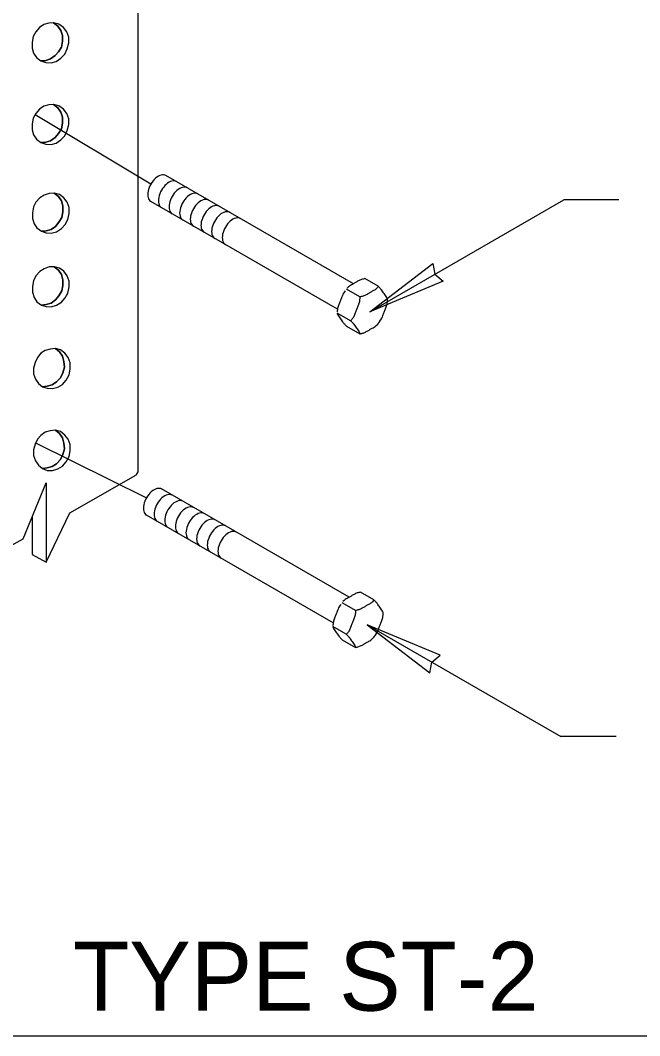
# Model space of a CAD drawing. Extents: x 99862 to 103680, y 99470 to 102076.
# Drawn here: x 100879.3 to 101059.2, y 99999.5 to 100294.4 of the extents above; entities that cross this region are included whole.
import ezdxf

# ---------------------------------------------------------------- set-up
doc = ezdxf.new("R2010")
doc.units = 0
for name, color, linetype in [('Level 1', 7, 'Continuous'), ('Level 13', 7, 'Continuous'), ('Level 15', 7, 'Continuous'), ('Level 2', 7, 'Continuous'), ('Level 20', 7, 'Continuous')]:
    doc.layers.add(name, color=color, linetype=linetype)

msp = doc.modelspace()

# ---------------------------------------------------------------- linework, layer by layer
at = {"layer": 'Level 1'}
msp.add_lwpolyline([(99862, 99999.5), (103151, 99999.5), (103151, 102075.5), (99862, 102075.5)], close=True, dxfattribs=at)
at = {"layer": 'Level 13'}
for p, q in [((100976.07, 100217.88), (100921.61, 100249.33)), ((100971.46, 100210.45), (100917.24, 100241.76)), ((100983.26, 100217.13), (100979.4, 100219.36)), ((100977.91, 100214.04), (100974.05, 100216.27)), ((100975.24, 100207.14), (100971.37, 100209.37)), ((100974.05, 100205.56), (100977.91, 100203.33)), ((100974.82, 100126.82), (100920.36, 100158.27)), ((100970.21, 100119.39), (100915.99, 100150.7)), ((100982.01, 100126.07), (100978.15, 100128.3)), ((100976.66, 100122.97), (100972.8, 100125.21)), ((100973.98, 100116.08), (100970.12, 100118.31)), ((100972.8, 100114.5), (100976.66, 100112.27))]:
    msp.add_line(p, q, dxfattribs=at)
for centre, start_param, end_param in [((100919.42, 100245.54), 6.283173, 9.424785), ((100922.52, 100243.76), 6.283174, 9.424783), ((100925.61, 100241.97), 6.283172, 9.424785), ((100928.7, 100240.19), 6.283179, 9.424784), ((100931.79, 100238.4), 6.283177, 9.424782), ((100934.88, 100236.62), 6.283174, 9.424785), ((100937.98, 100234.83), 6.283176, 9.424783), ((100941.07, 100233.05), 6.283178, 9.42478), ((100918.17, 100154.48), 6.283173, 9.424785), ((100921.26, 100152.69), 6.283174, 9.424783), ((100924.36, 100150.91), 6.283172, 9.424785), ((100927.45, 100149.12), 6.283179, 9.424784), ((100930.54, 100147.34), 6.283177, 9.424782), ((100933.63, 100145.55), 6.283174, 9.424785), ((100936.72, 100143.77), 6.283176, 9.424783), ((100939.82, 100141.98), 6.283178, 9.42478)]:
    msp.add_ellipse(centre, major_axis=(2.19, 3.78), ratio=0.57735, start_param=start_param, end_param=end_param, dxfattribs=at)
for points, degree in [([(100979.4, 100219.36), (100979.21, 100219.33), (100979.01, 100219.29), (100977.92, 100218.98), (100977.07, 100218.46), (100976.34, 100218.03), (100975.62, 100217.62), (100974.73, 100217.14), (100974.27, 100216.61)], 3), ([(100983.26, 100217.13), (100983.22, 100217.02), (100983.15, 100216.9), (100982.61, 100216.27), (100981.7, 100215.78), (100980.97, 100215.36), (100980.24, 100214.94), (100979.4, 100214.41), (100978.3, 100214.1), (100978.1, 100214.06), (100977.91, 100214.04)], 3), ([(100985.95, 100213.38), (100985.95, 100213.41), (100985.94, 100213.45), (100985.82, 100213.84), (100985.35, 100214.48), (100984.99, 100215), (100984.62, 100215.52), (100984.22, 100216.13), (100983.53, 100216.87), (100983.4, 100217), (100983.26, 100217.13)], 3), ([(100973.63, 100215.81), (100973.07, 100215.06), (100972.68, 100213.95), (100972.33, 100213.04), (100971.96, 100212.1), (100971.49, 100210.99), (100971.37, 100209.87), (100971.37, 100209.78), (100971.36, 100209.69)], 3), ([(100977.91, 100214.04), (100977.93, 100213.84), (100977.92, 100213.63), (100977.79, 100212.42), (100977.32, 100211.31), (100976.96, 100210.37), (100976.59, 100209.42), (100976.19, 100208.27), (100975.5, 100207.39), (100975.37, 100207.25), (100975.24, 100207.14)], 3), ([(100983.68, 100206.87), (100984.24, 100207.63), (100984.63, 100208.74), (100984.99, 100209.65), (100985.35, 100210.59), (100985.82, 100211.7), (100985.94, 100212.82), (100985.95, 100212.91), (100985.95, 100213)], 3), ([(100985.95, 100213), (100985.95, 100213.11), (100985.95, 100213.22), (100985.95, 100213.35), (100985.95, 100213.36), (100985.95, 100213.38)], 3), ([(100971.36, 100209.31), (100971.36, 100209.28), (100971.37, 100209.24), (100971.49, 100208.85), (100971.96, 100208.21), (100972.33, 100207.69), (100972.69, 100207.17), (100973.1, 100206.56), (100973.79, 100205.82), (100973.91, 100205.69), (100974.05, 100205.56)], 3), ([(100975.24, 100207.14), (100975.37, 100207.01), (100975.5, 100206.88), (100976.19, 100206.14), (100976.59, 100205.53), (100976.96, 100205.01), (100977.32, 100204.49), (100977.79, 100203.85), (100977.92, 100203.43), (100977.93, 100203.37), (100977.91, 100203.33)], 3), ([(100977.91, 100203.33), (100978.1, 100203.35), (100978.3, 100203.4), (100979.4, 100203.71), (100980.24, 100204.23), (100980.97, 100204.65), (100981.69, 100205.07), (100982.59, 100205.55), (100983.05, 100206.08)], 3), ([(100983.05, 100206.08), (100983.27, 100206.33), (100983.49, 100206.6), (100983.69, 100206.88)], 2), ([(100978.15, 100128.3), (100977.96, 100128.27), (100977.76, 100128.23), (100976.66, 100127.92), (100975.82, 100127.39), (100975.09, 100126.97), (100974.37, 100126.56), (100973.47, 100126.08), (100973.01, 100125.55)], 3), ([(100982.01, 100126.07), (100981.97, 100125.95), (100981.89, 100125.84), (100981.36, 100125.21), (100980.45, 100124.72), (100979.72, 100124.3), (100978.99, 100123.88), (100978.14, 100123.35), (100977.05, 100123.04), (100976.85, 100123), (100976.66, 100122.97)], 3), ([(100984.7, 100122.32), (100984.7, 100122.35), (100984.69, 100122.39), (100984.57, 100122.78), (100984.1, 100123.42), (100983.73, 100123.94), (100983.37, 100124.46), (100982.96, 100125.06), (100982.28, 100125.81), (100982.15, 100125.94), (100982.01, 100126.07)], 3), ([(100972.38, 100124.75), (100971.82, 100124), (100971.43, 100122.89), (100971.07, 100121.98), (100970.71, 100121.04), (100970.24, 100119.92), (100970.12, 100118.81), (100970.11, 100118.72), (100970.11, 100118.62)], 3), ([(100976.66, 100122.97), (100976.68, 100122.78), (100976.67, 100122.57), (100976.54, 100121.36), (100976.07, 100120.25), (100975.71, 100119.3), (100975.34, 100118.36), (100974.93, 100117.21), (100974.25, 100116.33), (100974.12, 100116.18), (100973.98, 100116.08)], 3), ([(100984.7, 100121.94), (100984.7, 100122.05), (100984.7, 100122.16), (100984.7, 100122.29), (100984.7, 100122.3), (100984.7, 100122.32)], 3), ([(100982.43, 100115.81), (100982.99, 100116.57), (100983.38, 100117.67), (100983.73, 100118.59), (100984.1, 100119.53), (100984.57, 100120.64), (100984.69, 100121.75), (100984.69, 100121.85), (100984.7, 100121.94)], 3), ([(100970.11, 100118.25), (100970.11, 100118.22), (100970.12, 100118.18), (100970.24, 100117.79), (100970.71, 100117.15), (100971.07, 100116.63), (100971.44, 100116.11), (100971.84, 100115.5), (100972.53, 100114.76), (100972.66, 100114.63), (100972.8, 100114.5)], 3), ([(100973.98, 100116.08), (100974.12, 100115.95), (100974.25, 100115.82), (100974.93, 100115.08), (100975.34, 100114.47), (100975.71, 100113.95), (100976.07, 100113.43), (100976.54, 100112.79), (100976.67, 100112.37), (100976.68, 100112.31), (100976.66, 100112.27)], 3), ([(100976.66, 100112.27), (100976.85, 100112.29), (100977.05, 100112.34), (100978.14, 100112.65), (100978.99, 100113.17), (100979.72, 100113.59), (100980.44, 100114.01), (100981.33, 100114.49), (100981.79, 100115.01)], 3), ([(100981.79, 100115.01), (100982.02, 100115.27), (100982.23, 100115.54), (100982.43, 100115.81)], 2)]:
    msp.add_open_spline(points, degree=degree, dxfattribs=at)
at = {"layer": 'Level 15'}
for p, q in [((100917.24, 100246.8), (100883.65, 100266.93)), ((100980.87, 100209.76), (101037.17, 100242.26)), ((101053.17, 100242.26), (101037.17, 100242.26)), ((100883.8, 100171.69), (100915.99, 100155.74)), ((100980.02, 100118.86), (101036.31, 100086.36)), ((101052.31, 100086.36), (101036.31, 100086.36))]:
    msp.add_line(p, q, dxfattribs=at)
for points in [[(100980.87, 100209.76), (100999.15, 100223.76), (100999.73, 100220.65), (101002.14, 100218.59)], [(100980.02, 100118.86), (100998.3, 100104.86), (100998.88, 100107.97), (101001.29, 100110.03)]]:
    msp.add_lwpolyline(points, close=True, dxfattribs=at)
at = {"layer": 'Level 2'}
msp.add_line((100893.69, 100151.33), (100912.86, 100162.29), dxfattribs=at)
for points in [[(100913.43, 100320.05), (100913.43, 100163.27), (100912.86, 100162.29)], [(100885.31, 100282.59), (100886.73, 100282.73), (100888.15, 100283.15), (100889.43, 100284.12), (100890.42, 100285.23), (100891.28, 100286.61), (100891.56, 100288.28), (100891.56, 100289.94), (100891.13, 100291.47), (100890.28, 100292.72), (100889, 100293.69), (100887.58, 100293.55), (100886.16, 100293.14), (100884.89, 100292.3), (100883.89, 100291.05), (100883.04, 100289.67), (100882.76, 100288), (100882.76, 100286.34), (100883.18, 100284.81), (100884.03, 100283.56), (100885.31, 100282.59)], [(100885.31, 100282.59), (100886.73, 100282.17), (100888.29, 100282.04), (100889.71, 100282.45), (100891.13, 100283.42), (100892.27, 100284.53), (100892.98, 100286.06), (100893.41, 100287.86), (100893.41, 100289.53), (100892.84, 100291.05), (100891.84, 100292.3), (100890.57, 100293.27), (100889, 100293.69), (100890.28, 100292.72), (100891.13, 100291.47), (100891.56, 100289.94), (100891.56, 100288.28), (100891.28, 100286.61), (100890.42, 100285.23), (100889.43, 100284.12), (100888.15, 100283.15), (100886.73, 100282.73), (100885.31, 100282.59)], [(100885.31, 100258.87), (100886.73, 100259.01), (100888.15, 100259.42), (100889.43, 100260.39), (100890.42, 100261.5), (100891.28, 100262.89), (100891.56, 100264.56), (100891.56, 100266.22), (100891.13, 100267.75), (100890.28, 100269), (100889, 100269.97), (100887.58, 100269.83), (100886.16, 100269.41), (100884.89, 100268.58), (100883.89, 100267.33), (100883.04, 100265.94), (100882.76, 100264.28), (100882.76, 100262.61), (100883.18, 100261.09), (100884.03, 100259.84), (100885.31, 100258.87)], [(100885.31, 100258.87), (100886.73, 100258.45), (100888.29, 100258.31), (100889.71, 100258.73), (100891.13, 100259.7), (100892.27, 100260.81), (100892.98, 100262.34), (100893.41, 100264.14), (100893.41, 100265.8), (100892.84, 100267.33), (100891.84, 100268.58), (100890.57, 100269.55), (100889, 100269.97), (100890.28, 100269), (100891.13, 100267.75), (100891.56, 100266.22), (100891.56, 100264.56), (100891.28, 100262.89), (100890.42, 100261.5), (100889.43, 100260.39), (100888.15, 100259.42), (100886.73, 100259.01), (100885.31, 100258.87)], [(100885.45, 100233.1), (100886.87, 100233.24), (100888.29, 100233.66), (100889.57, 100234.49), (100890.57, 100235.74), (100891.42, 100237.13), (100891.7, 100238.79), (100891.7, 100240.46), (100891.28, 100241.98), (100890.42, 100243.23), (100889.15, 100244.2), (100887.73, 100244.07), (100886.31, 100243.65), (100885.03, 100242.82), (100883.89, 100241.57), (100883.18, 100240.18), (100882.9, 100238.52), (100882.9, 100236.85), (100883.32, 100235.32), (100884.18, 100234.08), (100885.45, 100233.1)], [(100885.45, 100233.1), (100886.87, 100232.69), (100888.29, 100232.55), (100889.86, 100232.97), (100891.28, 100233.94), (100892.41, 100235.05), (100893.12, 100236.57), (100893.55, 100238.24), (100893.55, 100240.04), (100892.98, 100241.57), (100891.99, 100242.82), (100890.71, 100243.79), (100889.15, 100244.2), (100890.42, 100243.23), (100891.28, 100241.98), (100891.7, 100240.46), (100891.7, 100238.79), (100891.42, 100237.13), (100890.57, 100235.74), (100889.57, 100234.49), (100888.29, 100233.66), (100886.87, 100233.24), (100885.45, 100233.1)], [(100885.45, 100211.69), (100886.87, 100211.83), (100888.29, 100212.24), (100889.57, 100213.22), (100890.57, 100214.33), (100891.42, 100215.85), (100891.7, 100217.38), (100891.7, 100219.04), (100891.28, 100220.57), (100890.42, 100221.82), (100889.15, 100222.79), (100887.73, 100222.79), (100886.31, 100222.23), (100885.03, 100221.4), (100883.89, 100220.15), (100883.18, 100218.77), (100882.9, 100217.1), (100882.9, 100215.44), (100883.32, 100213.91), (100884.18, 100212.66), (100885.45, 100211.69)], [(100885.45, 100211.69), (100886.87, 100211.27), (100888.29, 100211.13), (100889.86, 100211.69), (100891.28, 100212.52), (100892.41, 100213.77), (100893.12, 100215.16), (100893.55, 100216.96), (100893.55, 100218.63), (100892.98, 100220.15), (100891.99, 100221.54), (100890.71, 100222.37), (100889.15, 100222.79), (100890.42, 100221.82), (100891.28, 100220.57), (100891.7, 100219.04), (100891.7, 100217.38), (100891.42, 100215.85), (100890.57, 100214.33), (100889.57, 100213.22), (100888.29, 100212.24), (100886.87, 100211.83), (100885.45, 100211.69)], [(100885.74, 100187.96), (100887.16, 100188.1), (100888.58, 100188.52), (100889.86, 100189.35), (100890.99, 100190.6), (100891.7, 100191.99), (100892.13, 100193.65), (100891.99, 100195.32), (100891.56, 100196.84), (100890.71, 100198.09), (100889.57, 100199.06), (100888.01, 100198.92), (100886.59, 100198.51), (100885.31, 100197.68), (100884.32, 100196.43), (100883.61, 100195.04), (100883.18, 100193.37), (100883.18, 100191.71), (100883.75, 100190.18), (100884.6, 100188.93), (100885.74, 100187.96)], [(100885.74, 100187.96), (100887.16, 100187.55), (100888.72, 100187.41), (100890.28, 100187.82), (100891.56, 100188.66), (100892.7, 100189.91), (100893.55, 100191.43), (100893.83, 100193.1), (100893.83, 100194.9), (100893.26, 100196.43), (100892.27, 100197.68), (100890.99, 100198.65), (100889.57, 100199.06), (100890.71, 100198.09), (100891.56, 100196.84), (100891.99, 100195.32), (100892.13, 100193.65), (100891.7, 100191.99), (100890.99, 100190.6), (100889.86, 100189.35), (100888.58, 100188.52), (100887.16, 100188.1), (100885.74, 100187.96)], [(100885.74, 100164.24), (100887.16, 100164.38), (100888.58, 100164.79), (100889.86, 100165.62), (100890.99, 100166.87), (100891.7, 100168.26), (100892.13, 100169.93), (100891.99, 100171.59), (100891.56, 100173.12), (100890.71, 100174.37), (100889.57, 100175.34), (100888.01, 100175.2), (100886.59, 100174.78), (100885.31, 100173.81), (100884.32, 100172.7), (100883.61, 100171.31), (100883.18, 100169.65), (100883.18, 100167.98), (100883.75, 100166.46), (100884.6, 100165.21), (100885.74, 100164.24)], [(100885.74, 100164.24), (100887.16, 100163.68), (100888.72, 100163.68), (100890.28, 100164.1), (100891.56, 100164.93), (100892.7, 100166.18), (100893.55, 100167.71), (100893.83, 100169.37), (100893.83, 100171.17), (100893.26, 100172.7), (100892.27, 100173.95), (100890.99, 100174.92), (100889.57, 100175.34), (100890.71, 100174.37), (100891.56, 100173.12), (100891.99, 100171.59), (100892.13, 100169.93), (100891.7, 100168.26), (100890.99, 100166.87), (100889.86, 100165.62), (100888.58, 100164.79), (100887.16, 100164.38), (100885.74, 100164.24)], [(100859.04, 100132.46), (100860.18, 100132.74), (100880.2, 100143.84), (100886.87, 100160.07), (100886.87, 100137.04), (100893.69, 100151.33)], [(100882.76, 100150.08), (100882.76, 100139.26), (100886.87, 100137.04)]]:
    msp.add_lwpolyline(points, dxfattribs=at)

# ---------------------------------------------------------------- texts
at = {"layer": 'Level 20'}
msp.add_text('TYPE ST-2', height=20, dxfattribs=at).set_placement((100894.65, 100006.76))

doc.saveas('drawing.dxf')
